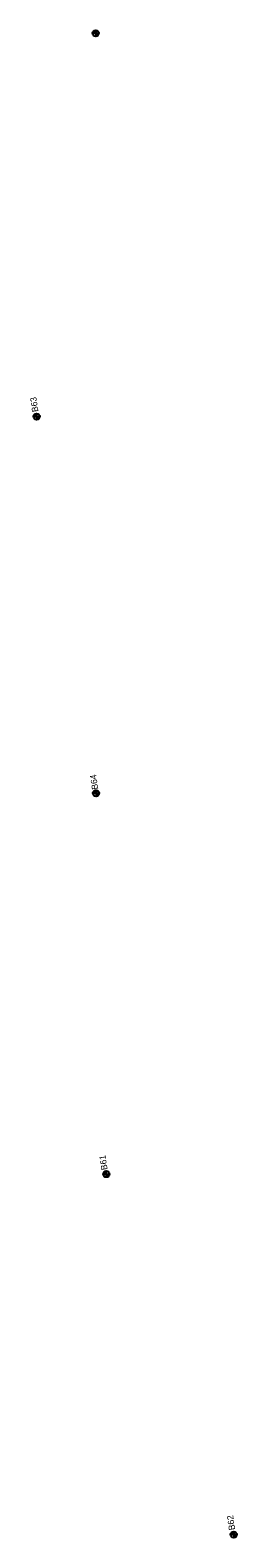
# Model space of a CAD drawing. Extents: x 327762 to 372792, y 127949 to 259367.
# Drawn here: x 359339 to 359667, y 163483 to 165868 of the extents above; entities that cross this region are included whole.
import ezdxf

# ---------------------------------------------------------------- set-up
doc = ezdxf.new("R2010")
doc.units = 0
for name, color, linetype in [('E_SOIL_BORE1 [KAPUR_CADDS_LEVELS]', 7, 'Continuous'), ('E_SOIL_BORE2 [KAPUR_CADDS_LEVELS]', 7, 'Continuous'), ('P_MARK', 7, 'Continuous')]:
    doc.layers.add(name, color=color, linetype=linetype)

msp = doc.modelspace()

# ---------------------------------------------------------------- linework, layer by layer
at = {"layer": 'P_MARK'}
for p, q in [((359437.8, 165863.3), (359447.8, 165863.3)), ((359442.8, 165868.3), (359442.8, 165858.3)), ((359344.2, 165256.8), (359354.2, 165256.8)), ((359349.2, 165261.8), (359349.2, 165251.8)), ((359438.4, 164660.9), (359448.4, 164660.9)), ((359443.4, 164665.9), (359443.4, 164655.9)), ((359454.6, 164058.3), (359464.6, 164058.3)), ((359459.6, 164063.3), (359459.6, 164053.3)), ((359656.6, 163487.9), (359666.6, 163487.9)), ((359661.6, 163492.9), (359661.6, 163482.9))]:
    msp.add_line(p, q, dxfattribs=at)
for centre in [(359442.8, 165863.3), (359349.2, 165256.8), (359443.4, 164660.9), (359459.6, 164058.3), (359661.6, 163487.9)]:
    msp.add_circle(centre, 5, dxfattribs=at)
for centre, radius, start, end in [((359442.8, 165863.3), 4.5, 89.9869, 179.9869), ((359442.8, 165863.3), 4, 89.9869, 179.9869), ((359442.8, 165863.3), 3.5, 89.9869, 179.9869), ((359442.8, 165863.3), 3, 89.9869, 179.9869), ((359442.8, 165863.3), 2.5, 89.9869, 179.9869), ((359442.8, 165863.3), 2, 89.9869, 179.9869), ((359442.8, 165863.3), 1.5, 89.9869, 179.9869), ((359442.8, 165863.3), 1, 89.9869, 179.9869), ((359442.8, 165863.3), 0.5, 89.9869, 179.9869), ((359442.8, 165863.3), 4.5, 269.9869, 359.9869), ((359442.8, 165863.3), 4, 269.9869, 359.9869), ((359442.8, 165863.3), 3.5, 269.9869, 359.9869), ((359442.8, 165863.3), 3, 269.9869, 359.9869), ((359442.8, 165863.3), 2.5, 269.9869, 359.9869), ((359442.8, 165863.3), 2, 269.9869, 359.9869), ((359442.8, 165863.3), 1.5, 269.9869, 359.9869), ((359442.8, 165863.3), 1, 269.9869, 359.9869), ((359442.8, 165863.3), 0.5, 269.9869, 359.9869), ((359349.2, 165256.8), 4.5, 89.9869, 179.9869), ((359349.2, 165256.8), 4, 89.9869, 179.9869), ((359349.2, 165256.8), 3.5, 89.9869, 179.9869), ((359349.2, 165256.8), 3, 89.9869, 179.9869), ((359349.2, 165256.8), 2.5, 89.9869, 179.9869), ((359349.2, 165256.8), 2, 89.9869, 179.9869), ((359349.2, 165256.8), 1.5, 89.9869, 179.9869), ((359349.2, 165256.8), 1, 89.9869, 179.9869), ((359349.2, 165256.8), 0.5, 89.9869, 179.9869), ((359349.2, 165256.8), 4.5, 269.9869, 359.9869), ((359349.2, 165256.8), 4, 269.9869, 359.9869), ((359349.2, 165256.8), 3.5, 269.9869, 359.9869), ((359349.2, 165256.8), 3, 269.9869, 359.9869), ((359349.2, 165256.8), 2.5, 269.9869, 359.9869), ((359349.2, 165256.8), 2, 269.9869, 359.9869), ((359349.2, 165256.8), 1.5, 269.9869, 359.9869), ((359349.2, 165256.8), 1, 269.9869, 359.9869), ((359349.2, 165256.8), 0.5, 269.9869, 359.9869), ((359443.4, 164660.9), 4.5, 89.9869, 179.9869), ((359443.4, 164660.9), 4, 89.9869, 179.9869), ((359443.4, 164660.9), 3.5, 89.9869, 179.9869), ((359443.4, 164660.9), 3, 89.9869, 179.9869), ((359443.4, 164660.9), 2.5, 89.9869, 179.9869), ((359443.4, 164660.9), 2, 89.9869, 179.9869), ((359443.4, 164660.9), 1.5, 89.9869, 179.9869), ((359443.4, 164660.9), 1, 89.9869, 179.9869), ((359443.4, 164660.9), 0.5, 89.9869, 179.9869), ((359443.4, 164660.9), 4.5, 269.9869, 359.9869), ((359443.4, 164660.9), 4, 269.9869, 359.9869), ((359443.4, 164660.9), 3.5, 269.9869, 359.9869), ((359443.4, 164660.9), 3, 269.9869, 359.9869), ((359443.4, 164660.9), 2.5, 269.9869, 359.9869), ((359443.4, 164660.9), 2, 269.9869, 359.9869), ((359443.4, 164660.9), 1.5, 269.9869, 359.9869), ((359443.4, 164660.9), 1, 269.9869, 359.9869), ((359443.4, 164660.9), 0.5, 269.9869, 359.9869), ((359459.6, 164058.3), 4.5, 89.9869, 179.9869), ((359459.6, 164058.3), 4, 89.9869, 179.9869), ((359459.6, 164058.3), 3.5, 89.9869, 179.9869), ((359459.6, 164058.3), 3, 89.9869, 179.9869), ((359459.6, 164058.3), 2.5, 89.9869, 179.9869), ((359459.6, 164058.3), 2, 89.9869, 179.9869), ((359459.6, 164058.3), 1.5, 89.9869, 179.9869), ((359459.6, 164058.3), 1, 89.9869, 179.9869), ((359459.6, 164058.3), 0.5, 89.9869, 179.9869), ((359459.6, 164058.3), 4.5, 269.9869, 359.9869), ((359459.6, 164058.3), 4, 269.9869, 359.9869), ((359459.6, 164058.3), 3.5, 269.9869, 359.9869), ((359459.6, 164058.3), 3, 269.9869, 359.9869), ((359459.6, 164058.3), 2.5, 269.9869, 359.9869), ((359459.6, 164058.3), 2, 269.9869, 359.9869), ((359459.6, 164058.3), 1.5, 269.9869, 359.9869), ((359459.6, 164058.3), 1, 269.9869, 359.9869), ((359459.6, 164058.3), 0.5, 269.9869, 359.9869), ((359661.6, 163487.9), 4.5, 89.9869, 179.9869), ((359661.6, 163487.9), 4, 89.9869, 179.9869), ((359661.6, 163487.9), 3.5, 89.9869, 179.9869), ((359661.6, 163487.9), 3, 89.9869, 179.9869), ((359661.6, 163487.9), 2.5, 89.9869, 179.9869), ((359661.6, 163487.9), 2, 89.9869, 179.9869), ((359661.6, 163487.9), 1.5, 89.9869, 179.9869), ((359661.6, 163487.9), 1, 89.9869, 179.9869), ((359661.6, 163487.9), 0.5, 89.9869, 179.9869), ((359661.6, 163487.9), 4.5, 269.9869, 359.9869), ((359661.6, 163487.9), 4, 269.9869, 359.9869), ((359661.6, 163487.9), 3.5, 269.9869, 359.9869), ((359661.6, 163487.9), 3, 269.9869, 359.9869), ((359661.6, 163487.9), 2.5, 269.9869, 359.9869), ((359661.6, 163487.9), 2, 269.9869, 359.9869), ((359661.6, 163487.9), 1.5, 269.9869, 359.9869), ((359661.6, 163487.9), 1, 269.9869, 359.9869), ((359661.6, 163487.9), 0.5, 269.9869, 359.9869)]:
    msp.add_arc(centre, radius, start, end, dxfattribs=at)

# ---------------------------------------------------------------- texts
at = {"layer": 'E_SOIL_BORE1 [KAPUR_CADDS_LEVELS]'}
for s, p in [('B63', (359352.1, 165264.9)), ('B64', (359447, 164667.6))]:
    msp.add_text(s, height=10, rotation=98.5151, dxfattribs=at).set_placement(p)
at = {"layer": 'E_SOIL_BORE2 [KAPUR_CADDS_LEVELS]'}
for s, p in [('B61', (359461.7, 164065.5)), ('B62', (359664, 163495.8))]:
    msp.add_text(s, height=10, rotation=98.5151, dxfattribs=at).set_placement(p)

doc.saveas('drawing.dxf')
